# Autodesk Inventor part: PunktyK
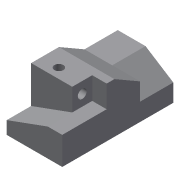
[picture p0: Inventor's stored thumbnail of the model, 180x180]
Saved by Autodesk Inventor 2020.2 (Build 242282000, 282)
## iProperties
Created: 2005-08
Part Number: PunktyK
Document SubType Name: Modeling
Designer: F.Stasiak
Manufacturer: Standard
Standards Organization: Custom
Material: Ogólny
Density: 1 g/cm^3
Appearance: Domyślna
Manager: www.cadconsulting.pl
Company: Fabian Stasiak CAD Consulting
Author: F.Stasiak
Subject: Zbiór ćwiczeń. Autodesk Inventor 2020. Kurs podstawowy
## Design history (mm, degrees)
sketch "Szkic1"
  geometry: L1 (0, 0)-(500, 0); L2 (500, 0)-(500, 400); L3 (500, 400)-(0, 400); L4 (0, 400)-(0, 0)
  constraints: 8 end point, 2 parallel, 1 horizontal, 1 perpendicular
  dimensions: "d0" = 500 distance of L2.end L3.end; "d1" = 400 distance of L3.end L1.start
extrude "Wyciągnięcie proste1" new body sketch "Szkic1" distance "d2" = 250; taper "d3" = 0 deg
sketch "Szkic2"
  geometry: L1 (0, 400)-(500, 400) reference; L2 (0, 0)-(0, 400) reference; L3 (0, 400)-(370, 400); L4 (370, 400)-(370, 220); L5 (370, 220)-(0, 220); L6 (0, 220)-(0, 400)
  constraints: 8 end point, 2 parallel, 1 horizontal, 1 perpendicular
  dimensions: "d4" = 370 distance of L4.end L5.end; "d5" = 180 distance of L3.end L4.end
extrude "Wyciągnięcie proste2" join sketch "Szkic2" distance "d6" = 200; taper "d7" = 0 deg
node "Płaszczyzna konstrukcyjna1"
feature "Podział1"
feature "Szkic powierzchni1" dims angle "d9" = -20 deg
sketch "Szkic3"
  geometry: L1 (0, 180)-(0, 0) reference; L2 (200, 0)-(0, 0) reference; L3 (200, 180)-(200, 0) reference; L4 (200, 180)-(0, 180) reference; L5 (0, 0)-(200, 180); C1 r 40 at (100, 90)
  constraints: 2 end point, 1 centre point, 1 midpoint
  dimensions: "d10" = 80 diameter of C1
extrude "Wyciągnięcie proste3" cut sketch "Szkic3" distance "d11" = 210; taper "d12" = 0 deg
sketch "Szkic4"
  geometry: L1 (160, 270)-(160, 350) reference; 1 further point
  constraints: 1 midpoint, 1 vertical alignment, 2 other
extrude "Wyciągnięcie proste4" cut sketch "Szkic4" stored distance "d13" = 210; taper "d14" = 0 deg
sketch "Szkic7"
  geometry: L1 (370, -250)-(500, -250) reference; L2 (500, 0)-(500, -250) reference; L3 (500, 0)-(0, 0) reference; L4 (0, 0)-(0, -450) reference; L5 (0, -450)-(370, -450) reference; L6 (370, -250)-(370, -450) reference; L7 (500, -250)-(500, -450); L8 (500, -450)-(370, -450)
  constraints: 4 end point, 1 parallel, 1 perpendicular
extrude "Wyciągnięcie proste5" join sketch "Szkic7" distance "d26" = 300; taper "d27" = 0 deg
node "Płaszczyzna konstrukcyjna7"
feature "Podział2"
feature "Szkic powierzchni2" dims angle "d29" = 30 deg
sketch "Szkic8"
  geometry: L1 (500, -317.209)-(0, -317.209) reference; L2 (500, 0)-(500, -317.209) reference; L3 (0, 0)-(500, 0) reference; L4 (0, -317.209)-(0, 0) reference; L5 (250, -317.209)-(250, 0)
  constraints: 2 end point, 2 midpoint
extrude "Wyciągnięcie proste6" join sketch "Szkic8" distance "d30" = 300; taper "d31" = 0 deg
sketch "Szkic9"
  geometry: L1 (250, 0)-(500, 0) reference; L2 (250, 0)-(250, -317.209) reference; L3 (250, -317.209)-(500, -158.605); L4 (500, -158.605)-(500, 0)
  constraints: 4 end point, 1 perpendicular
extrude "Wyciągnięcie proste7" join sketch "Szkic9" stored distance "d32" = 300; taper "d33" = 0 deg
node "Bryła1"
node "Korpusy bryłowe"
node "Korpusy powierzchniowe"
node "Pętla rzutowana1"
node "Pętla rzutowana2"
node "Pętla rzutowana3"
other parameters: "d8" = 0
